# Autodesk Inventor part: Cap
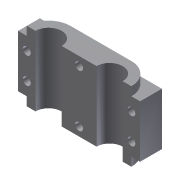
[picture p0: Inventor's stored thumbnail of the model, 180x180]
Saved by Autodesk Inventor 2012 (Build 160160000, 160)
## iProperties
Created: 2009-05
Part Number: Cap
Document SubType Name: Modeling
Designer: Sham
Density: 1 g/cm^3
Material: Default
Author: Sham
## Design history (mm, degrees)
sketch "Sketch1"
  geometry: L1 (-35, 12.5)-(35, 12.5); L2 (35, 12.5)-(35, 0); L3 (35, 0)-(-35, 0); L4 (-35, 0)-(-35, 12.5); 2 further points
  constraints: 8 end point, 2 parallel, 1 coincident, 1 horizontal, 1 midpoint, 1 perpendicular, 1 other
  dimensions: "d0" = 12.5 distance of L3.end L1.start; "d1" = 70 distance of L2.end L3.end
extrude "Extrusion1" new body sketch "Sketch1" stored distance "d2" = 30; taper "d3" = 0 deg
sketch "Sketch2"
  geometry: L1 (30, 0)-(-30, 0); L2 (-17.5, 12.5)-(17.5, 12.5); L3 (-35, 12.5)-(35, 12.5) reference; L4 (35, 0)-(-35, 0) reference; A1 r 12.5 centre (-17.5, 0) between (-17.5, 12.5) and (-30, 0); A2 r 12.5 centre (17.5, 0) between (30, 0) and (17.5, 12.5); 1 further point
  constraints: 4 end point, 4 point on circle, 2 centre point, 2 collinear, 2 horizontal, 1 equal radius, 1 point on line, 1 tangent, 1 other
  dimensions: "d4" = 60 distance of L1.start L1.end; "d5" = 30 distance of point (0, 0) L1.start; "d6" = 12.5 radius of A2; "d7" = 35 distance of A1.centre A2.centre (derived)
extrude "Extrusion2" join sketch "Sketch2" stored distance "d8" = 40; taper "d9" = 0 deg
sketch "Sketch3"
  geometry: L1 (-25, 0)-(-10, 0); L2 (10, 0)-(25, 0); A1 r 12.5 centre (-17.5, 0) between (-17.5, 12.5) and (-30, 0) reference; A2 r 12.5 centre (17.5, 0) between (30, 0) and (17.5, 12.5) reference; A3 r 7.5 centre (-17.5, 0) between (-10, 0) and (-25, 0); A4 r 7.5 centre (17.5, 0) between (25, 0) and (10, 0)
  constraints: 4 end point, 4 point on circle, 2 centre point, 2 coincident, 2 horizontal, 1 equal radius
  dimensions: "d10" = 7.5 radius of A3
hole "Hole2" diameter "d25" = 4.5; stored, may be unused: countersink angle "d29" = 90 deg, drill point angle "d31" = 118 deg; dims "d23" = 7.5, "d24" = 5, "d26" = 6, "d27" = 4, "d28" = 2, "d30" = 15
pattern_linear "Rectangular Pattern2" dims "d34" = 15
extrude "Extrusion3" cut sketch "Sketch3" stored distance "d38" = 10; taper "d39" = 0 deg
hole "Hole3" diameter "d42" = 4.5; stored, may be unused: countersink angle "d46" = 90 deg, drill point angle "d48" = 118 deg; dims "d40" = 5, "d41" = 30, "d43" = 6, "d44" = 4, "d45" = 2, "d47" = 13
pattern_linear "Rectangular Pattern3" dims "d51" = 30
body "Solid1"
